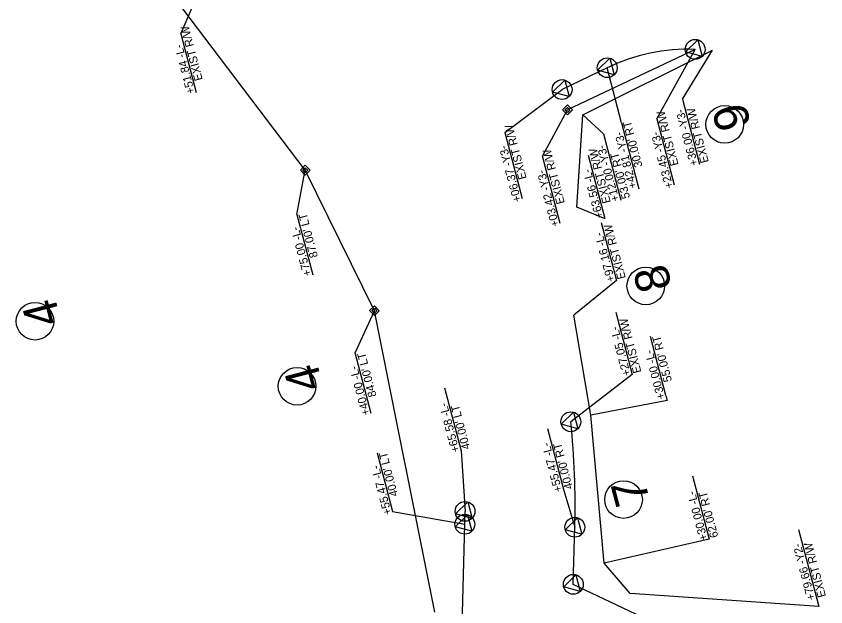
# Model space of a CAD drawing. Extents: x 1366833 to 1368739, y 877580 to 880469.
# Drawn here: x 1367161 to 1367750, y 879359 to 879788 of the extents above; entities that cross this region are included whole.
import ezdxf

# ---------------------------------------------------------------- set-up
doc = ezdxf.new("R2010")
doc.units = 0
for name, color, linetype in [('Exist Hydrographic River Shore', 7, 'Continuous'), ('Exist Structure Major Deck Tunnel Box Culvert', 7, 'Continuous'), ('P_RDY_Profile_Special_Ditch_L', 7, 'Continuous'), ('Prop Horizontal Alignment Station Label', 7, 'Continuous'), ('Prop North Arrow for Plan Sheets CELL', 7, 'Continuous'), ('Prop Shade Medium', 7, 'Continuous'), ('Scratch_Level_0', 7, 'Continuous'), ('Scratch_Level_3', 7, 'Continuous'), ('Sheet Clip Boundary CELL', 7, 'Continuous'), ('Sheet Professional Seal CELL', 7, 'Continuous'), ('Sheet Title Data Points CELL', 7, 'Continuous')]:
    doc.layers.add(name, color=color, linetype=linetype)

msp = doc.modelspace()

# ---------------------------------------------------------------- linework, layer by layer
at = {"layer": 'Exist Hydrographic River Shore'}
for p, q in [((1367590.93, 879750.54), (1367558.13, 879734.68)), ((1367474.63, 878948.36), (1367487.43, 879418.66)), ((1367566.27, 879374.99), (1367567.4, 879416.48))]:
    msp.add_line(p, q, dxfattribs=at)
for centre, radius, start, end in [((1367649.71, 879629.01), 135, 87.8069, 115.81035), ((1366977.61, 879432.52), 590, 358.44208, 5.89946), ((1366977.61, 879432.52), 510, 358.44208, 359.49516)]:
    msp.add_arc(centre, radius, start, end, dxfattribs=at)
at = {"layer": 'Exist Structure Major Deck Tunnel Box Culvert'}
for p, q in [((1367280.96, 879775.25), (1367309.09, 879840.47)), ((1367280.96, 879775.25), (1367292.14, 879732.61)), ((1367626.96, 879713.35), (1367654.88, 879763.91)), ((1367601.21, 879710.57), (1367590.93, 879750.54)), ((1367601.21, 879710.57), (1367613.8, 879662.51)), ((1367626.95, 879713.4), (1367639.54, 879665.34)), ((1367516.48, 879703.51), (1367529.08, 879655.45)), ((1367597.2, 879572.78), (1367609.06, 879527.55)), ((1367472.62, 879517.89), (1367484.63, 879472.04)), ((1367547.43, 879488.39), (1367559.29, 879443.16)), ((1367423.68, 879470.58), (1367434.85, 879427.94)), ((1367484.63, 879472.04), (1367487.59, 879428.03)), ((1367559.29, 879443.16), (1367567.4, 879416.48)), ((1367733.52, 879295.59), (1367566.27, 879374.99))]:
    msp.add_line(p, q, dxfattribs=at)
for points in [[(1367516.48, 879703.51), (1367558.13, 879734.68)], [(1367609.06, 879527.55), (1367564.49, 879493.17)], [(1367434.85, 879427.94), (1367487.43, 879418.66)]]:
    msp.add_lwpolyline(points, dxfattribs=at)
at = {"layer": 'P_RDY_Profile_Special_Ditch_L'}
for points in [[(1367562.03, 879723.49), (1367565.61, 879719.87), (1367561.99, 879716.29), (1367558.41, 879719.91)], [(1367562.02, 879721.69), (1367563.81, 879719.88), (1367562, 879718.09), (1367560.21, 879719.9)], [(1367371.44, 879679.62), (1367375.02, 879676), (1367371.4, 879672.42), (1367367.82, 879676.04)], [(1367371.43, 879677.82), (1367373.22, 879676.01), (1367371.41, 879674.22), (1367369.62, 879676.03)], [(1367421.66, 879577.54), (1367425.24, 879573.92), (1367421.62, 879570.34), (1367418.04, 879573.96)], [(1367421.65, 879575.74), (1367423.44, 879573.93), (1367421.63, 879572.14), (1367419.84, 879573.95)]]:
    msp.add_lwpolyline(points, close=True, dxfattribs=at)
at = {"layer": 'Prop Horizontal Alignment Station Label'}
for p, q in [((1367365.26, 879643.94), (1367376.8, 879599.92)), ((1367407.79, 879543.38), (1367421.64, 879573.94)), ((1367419.4, 879499.07), (1367407.79, 879543.38))]:
    msp.add_line(p, q, dxfattribs=at)
msp.add_lwpolyline([(1367365.26, 879643.94), (1367371.42, 879676.02)], dxfattribs=at)
at = {"layer": 'Prop North Arrow for Plan Sheets CELL'}
for p, q in [((1367371.42, 879676.02), (1367211.98, 879886.57)), ((1367421.64, 879573.94), (1367371.42, 879676.02)), ((1367465.68, 879354.76), (1367421.64, 879573.94))]:
    msp.add_line(p, q, dxfattribs=at)
at = {"layer": 'Prop Shade Medium'}
msp.add_line((1367654.88, 879763.91), (1367562.01, 879719.89), dxfattribs=at)
at = {"layer": 'Scratch_Level_0'}
for p, q in [((1367645.61, 879727.7), (1367658.02, 879680.34)), ((1367588.17, 879702.47), (1367600.79, 879654.32)), ((1367589.48, 879640.7), (1367577.43, 879686.67)), ((1367586.63, 879638.04), (1367597.71, 879595.78)), ((1367633.66, 879512.19), (1367622.41, 879555.11)), ((1367634.56, 879508.74), (1367579.07, 879497.93)), ((1367633.66, 879512.19), (1367634.56, 879508.74)), ((1367652.95, 879453.8), (1367665.03, 879407.73)), ((1367730.07, 879414.82), (1367743.28, 879364.41)), ((1367665.03, 879407.73), (1367588.7, 879390.43)), ((1367744.71, 879358.96), (1367607.57, 879368.3)), ((1367743.28, 879364.41), (1367744.71, 879358.96))]:
    msp.add_line(p, q, dxfattribs=at)
for points in [[(1367645.61, 879727.7), (1367667.42, 879763.43)], [(1367588.17, 879702.47), (1367573.21, 879716.42)], [(1367589.48, 879640.7), (1367568.78, 879649.09)], [(1367597.71, 879595.78), (1367566.62, 879570.71)]]:
    msp.add_lwpolyline(points, dxfattribs=at)
at = {"layer": 'Scratch_Level_3'}
for p, q in [((1367654.88, 879763.91), (1367654.88, 879763.91)), ((1367590.93, 879750.54), (1367590.93, 879750.54)), ((1367558.13, 879734.68), (1367558.13, 879734.68)), ((1367562.01, 879719.89), (1367562.01, 879719.89)), ((1367371.42, 879676.02), (1367371.42, 879676.02)), ((1367421.64, 879573.94), (1367421.64, 879573.94)), ((1367564.49, 879493.17), (1367564.49, 879493.17)), ((1367487.59, 879428.03), (1367487.59, 879428.03)), ((1367487.43, 879418.66), (1367487.43, 879418.66)), ((1367567.4, 879416.48), (1367567.4, 879416.48)), ((1367566.27, 879374.99), (1367566.27, 879374.99))]:
    msp.add_line(p, q, dxfattribs=at)
for points in [[(1367647.9, 879762.08), (1367656.77, 879770.86), (1367659.96, 879758.79)], [(1367583.96, 879748.71), (1367592.83, 879757.49), (1367596.02, 879745.42)], [(1367551.15, 879732.85), (1367560.02, 879741.62), (1367563.21, 879729.56)], [(1367557.51, 879491.34), (1367566.38, 879500.11), (1367569.57, 879488.05)], [(1367480.62, 879426.2), (1367489.49, 879434.98), (1367492.68, 879422.91)], [(1367480.45, 879416.83), (1367489.32, 879425.6), (1367492.51, 879413.54)], [(1367560.42, 879414.65), (1367569.29, 879423.43), (1367572.48, 879411.37)], [(1367559.29, 879373.16), (1367568.16, 879381.94), (1367571.35, 879369.87)]]:
    msp.add_lwpolyline(points, close=True, dxfattribs=at)
for centre in [(1367654.88, 879763.91), (1367590.93, 879750.54), (1367558.13, 879734.68), (1367564.49, 879493.17), (1367487.59, 879428.03), (1367487.43, 879418.66), (1367567.4, 879416.48), (1367566.27, 879374.99)]:
    msp.add_circle(centre, 7.2, dxfattribs=at)
at = {"layer": 'Sheet Clip Boundary CELL'}
for p, q in [((1367543.98, 879686.16), (1367562.01, 879719.89)), ((1367556.76, 879637.37), (1367543.98, 879686.16))]:
    msp.add_line(p, q, dxfattribs=at)
at = {"layer": 'Sheet Professional Seal CELL'}
for p, q in [((1367676.36, 879709.37), (1367676.36, 879709.37)), ((1367618.97, 879591.91), (1367618.97, 879591.91)), ((1367174.91, 879566.26), (1367174.91, 879566.26)), ((1367365.43, 879518.95), (1367365.43, 879518.95)), ((1367602.79, 879436.63), (1367602.79, 879436.63))]:
    msp.add_line(p, q, dxfattribs=at)
for centre in [(1367676.36, 879709.37), (1367618.97, 879591.91), (1367174.91, 879566.26), (1367365.43, 879518.95), (1367602.79, 879436.63)]:
    msp.add_circle(centre, 13.67, dxfattribs=at)
at = {"layer": 'Sheet Title Data Points CELL'}
for points in [[(1367568.78, 879649.09), (1367573.21, 879716.42), (1367667.42, 879763.43)], [(1367588.7, 879390.43), (1367579.07, 879497.93), (1367566.62, 879570.71)], [(1367607.57, 879368.3), (1367588.7, 879390.43), (1367588.7, 879390.43)]]:
    msp.add_lwpolyline(points, dxfattribs=at)

# ---------------------------------------------------------------- texts
at = {"layer": 'Exist Structure Major Deck Tunnel Box Culvert'}
for s, p in [('EXIST R/W', (1367296.87, 879741.89)), ('+51.84 -L-', (1367291.23, 879732.38)), ('EXIST R/W', (1367642.86, 879680.04)), ('EXIST R/W', (1367532.39, 879670.15)), ("30.00' RT", (1367616.66, 879678.95)), ('+42.81 -Y3-', (1367612.56, 879663.57)), ('+23.45 -Y3-', (1367639.03, 879663.63)), ('+06.37 -Y3-', (1367528.56, 879653.73)), ('EXIST R/W', (1367615.83, 879529.32)), ('+27.05 -L-', (1367608.09, 879527.29)), ('+65.58 -L-', (1367483.66, 879471.79)), ("40.00' LT", (1367491.4, 879473.82)), ('+55.47 -L-', (1367558.32, 879442.91)), ("40.00' RT", (1367566.06, 879444.93)), ("40.00' LT", (1367438.95, 879439.65)), ('+55.47 -L-', (1367434.31, 879426.33))]:
    msp.add_text(s, height=6, rotation=104.68512, dxfattribs=at).set_placement(p)
at = {"layer": 'Prop Horizontal Alignment Station Label'}
for s, p in [("87.00' LT", (1367380.65, 879613.21)), ('+75.00 -L-', (1367375.88, 879599.86)), ("84.00' LT", (1367423.27, 879511.93)), ('+40.00 -L-', (1367418.5, 879498.57))]:
    msp.add_text(s, height=6, rotation=104.68512, dxfattribs=at).set_placement(p)
at = {"layer": 'Scratch_Level_0'}
for s, height, p in [('+36.00 -Y3-', 6, (1367657.06, 879680.09)), ('EXIST R/W', 6, (1367664.8, 879682.12)), ('9', 25, (1367695.62, 879708.72)), ('EXIST R/W', 6, (1367593.55, 879652.78)), ('+12.00 -Y3-', 6, (1367599.82, 879654.07)), ("53.00' RT", 6, (1367607.56, 879656.1)), ('+63.56 -L-', 6, (1367588.15, 879641.85)), ('EXIST R/W', 6, (1367604.44, 879597.7)), ('+97.16 -L-', 6, (1367596.7, 879595.67)), ('8', 25, (1367638.22, 879591.27)), ('4', 25, (1367194.07, 879565.98)), ("55.00' RT", 6, (1367638.08, 879522.94)), ('+30.00 -L-', 6, (1367633.13, 879510.27)), ('4', 25, (1367384.59, 879518.67)), ('7', 25, (1367622.1, 879435.78)), ('+30.00 -L-', 6, (1367664.02, 879407.62)), ("62.00' RT", 6, (1367671.76, 879409.64)), ('+79.66 -Y2-', 6, (1367742.27, 879364.3)), ('EXIST R/W', 6, (1367750.01, 879366.33))]:
    msp.add_text(s, height=height, rotation=104.68512, dxfattribs=at).set_placement(p)
at = {"layer": 'Sheet Clip Boundary CELL'}
for s, p in [('EXIST R/W', (1367560.1, 879652.25)), ('+03.42 -Y3-', (1367556.14, 879635.8))]:
    msp.add_text(s, height=6, rotation=104.68512, dxfattribs=at).set_placement(p)

doc.saveas('drawing.dxf')
